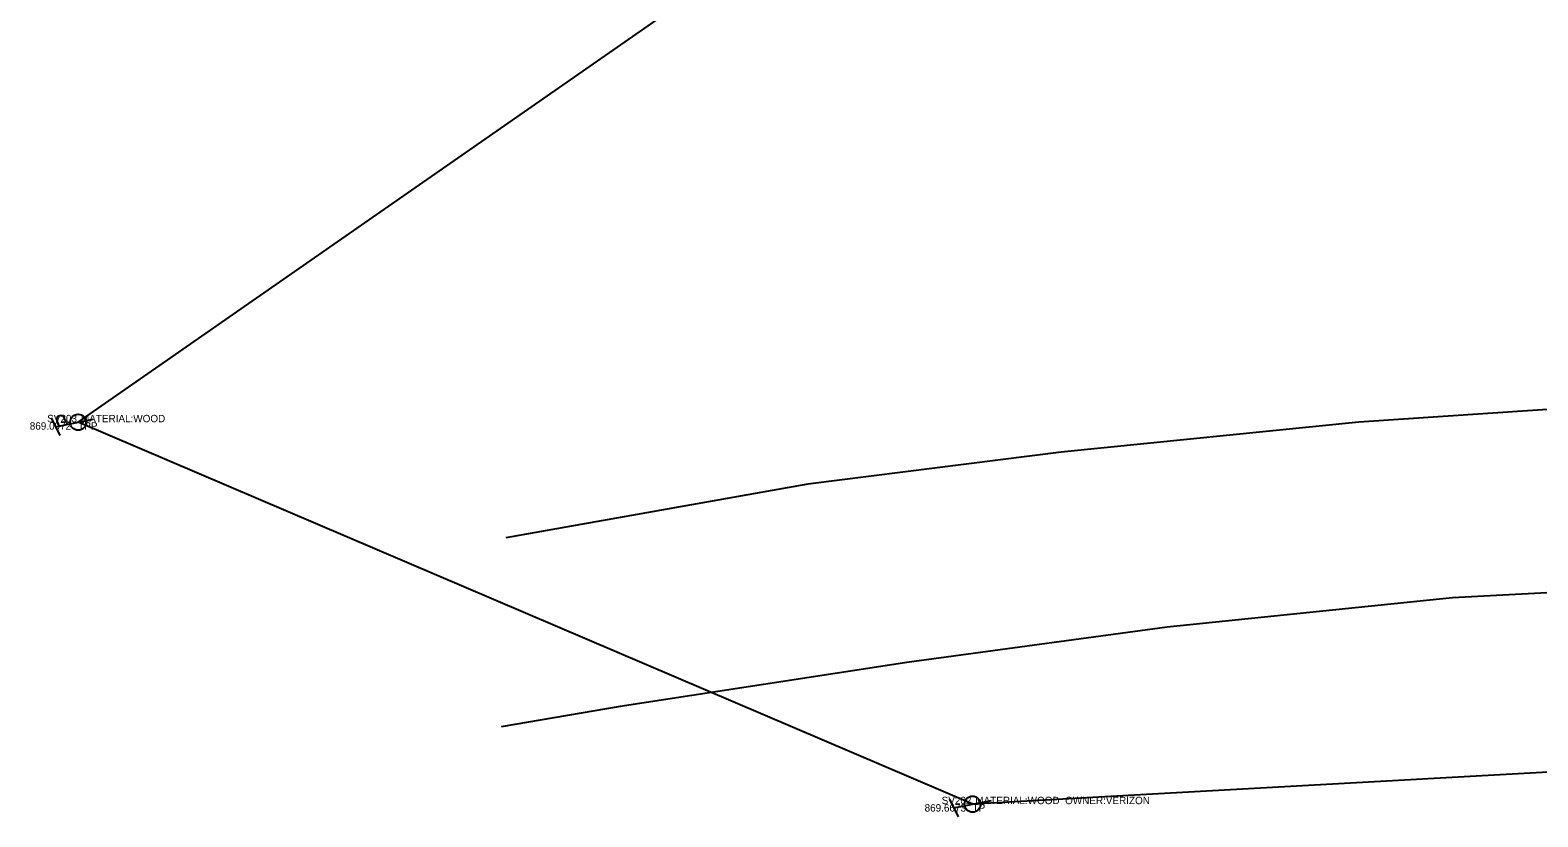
# Model space of a CAD drawing. Extents: x 1715717 to 1717046, y 393954 to 396000.
# Drawn here: x 1716322.9 to 1716444.9, y 394105.7 to 394169.3 of the extents above; entities that cross this region are included whole.
import ezdxf

# ---------------------------------------------------------------- set-up
doc = ezdxf.new("R2010")
doc.units = 0
for name, color, linetype in [('PV_X_EOP', 7, 'Continuous'), ('SV_X_Text_Comment', 7, 'Continuous'), ('SV_X_Text_Description', 7, 'Continuous'), ('SV_X_Text_Elevation', 7, 'Continuous'), ('SV_X_Text_Name', 7, 'Continuous'), ('UT_X_Misc_Cells', 7, 'Continuous'), ('UT_X_Overhead_Electric', 7, 'Continuous'), ('UT_X_Overhead_Telecom', 7, 'Continuous'), ('UT_X_Telecom_Cells', 7, 'Continuous')]:
    doc.layers.add(name, color=color, linetype=linetype)

msp = doc.modelspace()

# ---------------------------------------------------------------- linework, layer by layer
at = {"layer": 'PV_X_EOP'}
for p, q in [((1716451.81, 394139.01), (1716430.42, 394137.58)), ((1716430.42, 394137.58), (1716406.35, 394135.15)), ((1716406.35, 394135.15), (1716385.85, 394132.58)), ((1716385.85, 394132.58), (1716361.41, 394128.24)), ((1716454.61, 394124.26), (1716438, 394123.37)), ((1716438, 394123.37), (1716414.93, 394121.01)), ((1716414.93, 394121.01), (1716393.86, 394118.15)), ((1716393.86, 394118.15), (1716370.65, 394114.58)), ((1716370.65, 394114.58), (1716361.01, 394112.93))]:
    msp.add_line(p, q, dxfattribs=at)
at = {"layer": 'UT_X_Misc_Cells'}
for p, q in [((1716324.6, 394137.93), (1716325.31, 394136.5)), ((1716324.96, 394137.22), (1716328, 394137.82)), ((1716325.26, 394137.28), (1716325.08, 394137.66)), ((1716325.91, 394137.41), (1716325.65, 394137.94))]:
    msp.add_line(p, q, dxfattribs=at)
msp.add_circle((1716326.79, 394137.58), 0.65, dxfattribs=at)
msp.add_arc((1716325.36, 394137.8), 0.319, 25.1605, 207.4071, dxfattribs=at)
at = {"layer": 'UT_X_Overhead_Electric'}
msp.add_line((1716326.79, 394137.58), (1716495.47, 394254.94), dxfattribs=at)
at = {"layer": 'UT_X_Overhead_Telecom'}
for p, q in [((1716399.18, 394106.67), (1716326.79, 394137.58)), ((1716504.84, 394112.54), (1716399.18, 394106.67))]:
    msp.add_line(p, q, dxfattribs=at)
at = {"layer": 'UT_X_Telecom_Cells'}
for p, q in [((1716397.3, 394107.09), (1716398, 394105.65)), ((1716397.65, 394106.37), (1716400.7, 394106.98))]:
    msp.add_line(p, q, dxfattribs=at)
msp.add_circle((1716399.17, 394106.68), 0.65, dxfattribs=at)

# ---------------------------------------------------------------- texts
at = {"layer": 'SV_X_Text_Comment'}
for s, p in [('TPP', (1716326.79, 394136.98)), ('TP', (1716399.17, 394106.08))]:
    msp.add_text(s, height=0.6, dxfattribs=at).set_placement(p)
at = {"layer": 'SV_X_Text_Description'}
for s, p in [(' MATERIAL:WOOD ', (1716326.79, 394137.58)), (' MATERIAL:WOOD  OWNER:VERIZON ', (1716399.17, 394106.68))]:
    msp.add_text(s, height=0.6, dxfattribs=at).set_placement(p)
at = {"layer": 'SV_X_Text_Elevation'}
for s, p in [('869.0972', (1716322.87, 394136.98)), ('869.6673', (1716395.29, 394106.08))]:
    msp.add_text(s, height=0.6, dxfattribs=at).set_placement(p)
at = {"layer": 'SV_X_Text_Name'}
for s, p in [('SV203', (1716324.28, 394137.58)), ('SV202', (1716396.67, 394106.68))]:
    msp.add_text(s, height=0.6, dxfattribs=at).set_placement(p)

doc.saveas('drawing.dxf')
